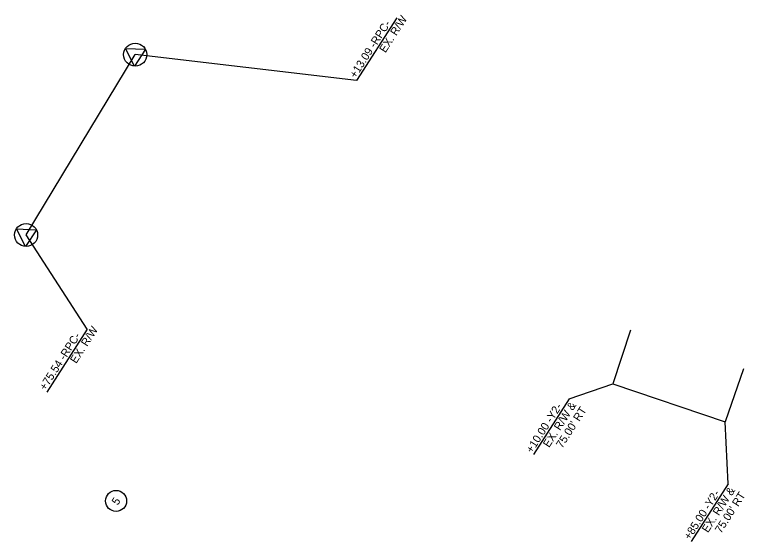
# Model space of a CAD drawing. Extents: x 2345854 to 2349056, y 842589 to 845145.
# Drawn here: x 2347564.4 to 2348020, y 842984.3 to 843313.4 of the extents above; entities that cross this region are included whole.
import ezdxf

# ---------------------------------------------------------------- set-up
doc = ezdxf.new("R2010")
doc.units = 0
for name, color, linetype in [('Prop Easement Construction', 7, 'Continuous'), ('Prop Easement Construction Station Offsets', 7, 'Continuous'), ('Prop Parcel Number Text', 7, 'Continuous'), ('Prop ROW Marker CELL', 7, 'Continuous'), ('Prop ROW RW CA Lines', 7, 'Continuous'), ('Prop ROW Station Offsets', 7, 'Continuous')]:
    doc.layers.add(name, color=color, linetype=linetype)

msp = doc.modelspace()

# ---------------------------------------------------------------- linework, layer by layer
at = {"layer": 'Prop Easement Construction'}
for p, q in [((2347948.82, 843116.16), (2347937.88, 843082.81)), ((2348019.36, 843092.12), (2348008.05, 843058.99)), ((2347937.88, 843082.81), (2348008.05, 843058.99))]:
    msp.add_line(p, q, dxfattribs=at)
at = {"layer": 'Prop Easement Construction Station Offsets'}
for p, q in [((2347910.64, 843073.4), (2347888.25, 843038.48)), ((2348009.83, 843020.19), (2347986.79, 842984.27))]:
    msp.add_line(p, q, dxfattribs=at)
for points in [[(2347910.64, 843073.4), (2347937.88, 843082.81)], [(2348009.83, 843020.19), (2348008.05, 843058.99)]]:
    msp.add_lwpolyline(points, dxfattribs=at)
at = {"layer": 'Prop Parcel Number Text'}
msp.add_circle((2347627.74, 843009.56), 6.56, dxfattribs=at)
at = {"layer": 'Prop ROW Marker CELL'}
for p, q in [((2347639.66, 843288.37), (2347639.66, 843288.37)), ((2347571.58, 843175.7), (2347571.58, 843175.7))]:
    msp.add_line(p, q, dxfattribs=at)
for points in [[(2347639.32, 843281.17), (2347633.6, 843292.26), (2347646.06, 843291.69)], [(2347571.24, 843168.49), (2347565.52, 843179.58), (2347577.98, 843179.01)]]:
    msp.add_lwpolyline(points, close=True, dxfattribs=at)
for centre in [(2347639.66, 843288.37), (2347571.58, 843175.7)]:
    msp.add_circle(centre, 7.2, dxfattribs=at)
at = {"layer": 'Prop ROW RW CA Lines'}
msp.add_line((2347571.58, 843175.7), (2347639.66, 843288.37), dxfattribs=at)
at = {"layer": 'Prop ROW Station Offsets'}
for p, q in [((2347802.94, 843311.37), (2347777.88, 843272.29)), ((2347609.7, 843116.95), (2347584.41, 843077.51))]:
    msp.add_line(p, q, dxfattribs=at)
for points in [[(2347777.88, 843272.29), (2347639.66, 843288.37)], [(2347609.7, 843116.95), (2347571.58, 843175.7)]]:
    msp.add_lwpolyline(points, dxfattribs=at)

# ---------------------------------------------------------------- texts
at = {"layer": 'Prop Easement Construction Station Offsets'}
for s, p in [('+10.00 -Y2-', (2347887.38, 843039.05)), ('EX. R/W &', (2347898.02, 843042.53)), ("75.00' RT", (2347906.17, 843042.11)), ('+85.00 -Y2-', (2347985.92, 842984.83)), ('EX. R/W &', (2347997.21, 842989.32)), ("75.00' RT", (2348005.36, 842988.9))]:
    msp.add_text(s, height=5, rotation=57.3281, dxfattribs=at).set_placement(p)
at = {"layer": 'Prop Parcel Number Text'}
msp.add_text('5', height=5, rotation=57.3281, dxfattribs=at).set_placement((2347628.77, 843006.52))
at = {"layer": 'Prop ROW Station Offsets'}
for s, p in [('EX. R/W', (2347795.86, 843289.13)), ('+13.09 -RPC-', (2347777.26, 843273.25)), ('EX. R/W', (2347602.82, 843095.03)), ('+75.54 -RPC-', (2347583.58, 843078.14))]:
    msp.add_text(s, height=5, rotation=57.3281, dxfattribs=at).set_placement(p)

doc.saveas('drawing.dxf')
